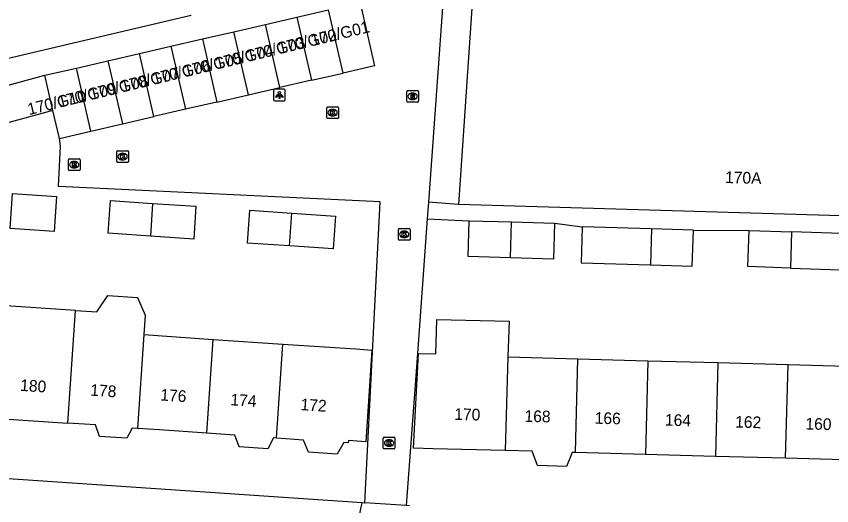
# Model space of a CAD drawing. Extents: x 159053 to 160041, y 380450 to 381422.
# Drawn here: x 159304.1 to 159374, y 381196.2 to 381238.1 of the extents above; entities that cross this region are included whole.
import ezdxf

# ---------------------------------------------------------------- set-up
doc = ezdxf.new("R2010")
doc.units = 0
for name, color, linetype in [('IMGEO_Kolk', 7, 'Continuous'), ('IMGEO_Lichtpunt', 7, 'Continuous'), ('IMGEO_Pand', 7, 'Continuous'), ('IMGEO_Pand_nummerreeks', 7, 'Continuous'), ('IMGEO_Rijbaan_lokaal_open', 7, 'Continuous'), ('IMGEO_Rioolput', 7, 'Continuous'), ('IMGEO_Voetpad_open', 7, 'Continuous')]:
    doc.layers.add(name, color=color, linetype=linetype)

msp = doc.modelspace()

# ---------------------------------------------------------------- linework, layer by layer
at = {"layer": 'IMGEO_Kolk'}
for p, q in [((159330.708, 381229.42), (159330.708, 381230.272)), ((159330.783, 381230.346), (159331.635, 381230.346)), ((159331.196, 381230.126), (159331.221, 381230.126)), ((159331.709, 381230.272), (159331.709, 381229.42)), ((159331.219, 381229.566), (159331.194, 381229.566)), ((159331.635, 381229.346), (159330.783, 381229.346)), ((159312.697, 381225.665), (159312.697, 381226.517)), ((159312.772, 381226.591), (159313.624, 381226.591)), ((159313.185, 381226.371), (159313.21, 381226.371)), ((159313.698, 381226.517), (159313.698, 381225.665)), ((159313.624, 381225.591), (159312.772, 381225.591)), ((159313.208, 381225.811), (159313.183, 381225.811)), ((159336.848, 381218.992), (159336.848, 381219.844)), ((159336.923, 381219.918), (159337.775, 381219.918)), ((159337.336, 381219.698), (159337.361, 381219.698)), ((159337.849, 381219.844), (159337.849, 381218.992)), ((159337.775, 381218.918), (159336.923, 381218.918)), ((159337.359, 381219.138), (159337.334, 381219.138)), ((159335.556, 381201.107), (159335.556, 381201.959)), ((159335.631, 381202.033), (159336.483, 381202.033)), ((159336.044, 381201.813), (159336.069, 381201.813)), ((159336.557, 381201.959), (159336.557, 381201.107)), ((159336.483, 381201.033), (159335.631, 381201.033)), ((159336.067, 381201.253), (159336.042, 381201.253))]:
    msp.add_line(p, q, dxfattribs=at)
for points in [[(159330.708, 381229.42), (159330.708, 381230.272)], [(159330.783, 381230.346), (159331.635, 381230.346)], [(159331.709, 381230.272), (159331.709, 381229.42)], [(159331.029, 381230.046), (159331.152, 381230.046), (159331.152, 381229.895), (159331.282, 381230.046), (159331.446, 381230.046), (159331.3, 381229.895), (159331.453, 381229.646), (159331.301, 381229.646), (159331.216, 381229.81), (159331.152, 381229.743), (159331.152, 381229.646), (159331.029, 381229.646), (159331.029, 381230.046)], [(159331.635, 381229.346), (159330.783, 381229.346)], [(159312.697, 381225.665), (159312.697, 381226.517)], [(159312.772, 381226.591), (159313.624, 381226.591)], [(159313.018, 381226.291), (159313.141, 381226.291), (159313.141, 381226.14), (159313.271, 381226.291), (159313.435, 381226.291), (159313.289, 381226.14), (159313.442, 381225.891), (159313.29, 381225.891), (159313.205, 381226.055), (159313.141, 381225.988), (159313.141, 381225.891), (159313.018, 381225.891), (159313.018, 381226.291)], [(159313.698, 381226.517), (159313.698, 381225.665)], [(159313.624, 381225.591), (159312.772, 381225.591)], [(159336.848, 381218.992), (159336.848, 381219.844)], [(159336.923, 381219.918), (159337.775, 381219.918)], [(159337.169, 381219.618), (159337.292, 381219.618), (159337.292, 381219.467), (159337.422, 381219.618), (159337.586, 381219.618), (159337.44, 381219.467), (159337.593, 381219.218), (159337.441, 381219.218), (159337.356, 381219.382), (159337.292, 381219.315), (159337.292, 381219.218), (159337.169, 381219.218), (159337.169, 381219.618)], [(159337.849, 381219.844), (159337.849, 381218.992)], [(159337.775, 381218.918), (159336.923, 381218.918)], [(159335.556, 381201.107), (159335.556, 381201.959)], [(159335.631, 381202.033), (159336.483, 381202.033)], [(159335.877, 381201.733), (159336, 381201.733), (159336, 381201.582), (159336.13, 381201.733), (159336.294, 381201.733), (159336.148, 381201.582), (159336.301, 381201.333), (159336.149, 381201.333), (159336.064, 381201.497), (159336, 381201.43), (159336, 381201.333), (159335.877, 381201.333), (159335.877, 381201.733)], [(159336.557, 381201.959), (159336.557, 381201.107)], [(159336.483, 381201.033), (159335.631, 381201.033)]]:
    msp.add_lwpolyline(points, dxfattribs=at)
for centre, start, end in [((159330.785, 381230.27), 91.55205, 178.44795), ((159330.785, 381230.27), 91.55205, 178.44795), ((159331.633, 381230.27), 1.55205, 88.44795), ((159331.633, 381230.27), 1.55205, 88.44795), ((159330.785, 381229.422), 181.55205, 268.44795), ((159330.785, 381229.422), 181.55205, 268.44795), ((159331.633, 381229.422), 271.55205, 358.44795), ((159331.633, 381229.422), 271.55205, 358.44795), ((159312.774, 381226.515), 91.55205, 178.44795), ((159312.774, 381226.515), 91.55205, 178.44795), ((159313.622, 381226.515), 1.55205, 88.44795), ((159313.622, 381226.515), 1.55205, 88.44795), ((159312.774, 381225.667), 181.55205, 268.44795), ((159312.774, 381225.667), 181.55205, 268.44795), ((159313.622, 381225.667), 271.55205, 358.44795), ((159313.622, 381225.667), 271.55205, 358.44795), ((159336.925, 381219.842), 91.55205, 178.44795), ((159336.925, 381219.842), 91.55205, 178.44795), ((159337.773, 381219.842), 1.55205, 88.44795), ((159337.773, 381219.842), 1.55205, 88.44795), ((159336.925, 381218.994), 181.55205, 268.44795), ((159336.925, 381218.994), 181.55205, 268.44795), ((159337.773, 381218.994), 271.55205, 358.44795), ((159337.773, 381218.994), 271.55205, 358.44795), ((159335.633, 381201.957), 91.55205, 178.44795), ((159335.633, 381201.957), 91.55205, 178.44795), ((159336.481, 381201.957), 1.55205, 88.44795), ((159336.481, 381201.957), 1.55205, 88.44795), ((159335.633, 381201.109), 181.55205, 268.44795), ((159335.633, 381201.109), 181.55205, 268.44795), ((159336.481, 381201.109), 271.55205, 358.44795), ((159336.481, 381201.109), 271.55205, 358.44795)]:
    msp.add_arc(centre, 0.0765, start, end, dxfattribs=at)
for centre, major_axis, ratio, start_param, end_param in [((159331.195, 381229.846), (-0.387, 0.002), 0.722429, 4.712389, 7.853982), ((159331.22, 381229.846), (-0.39, 0.002), 0.717154, 1.570796, 4.712389), ((159313.184, 381226.091), (-0.387, 0.002), 0.722429, 4.712389, 7.853982), ((159313.209, 381226.091), (-0.39, 0.002), 0.717154, 1.570796, 4.712389), ((159337.335, 381219.418), (-0.387, 0.002), 0.722429, 4.712389, 7.853982), ((159337.36, 381219.418), (-0.39, 0.002), 0.717154, 1.570796, 4.712389), ((159336.043, 381201.533), (-0.387, 0.002), 0.722429, 4.712389, 7.853982), ((159336.068, 381201.533), (-0.39, 0.002), 0.717154, 1.570796, 4.712389)]:
    msp.add_ellipse(centre, major_axis=major_axis, ratio=ratio, start_param=start_param, end_param=end_param, dxfattribs=at)
at = {"layer": 'IMGEO_Lichtpunt'}
for p, q in [((159326.15, 381231.764), (159326.15, 381230.957)), ((159326.15, 381231.764), (159326.15, 381230.957)), ((159327.052, 381231.859), (159326.244, 381231.859)), ((159327.052, 381231.859), (159326.244, 381231.859)), ((159327.146, 381230.957), (159327.146, 381231.764)), ((159327.146, 381230.957), (159327.146, 381231.764)), ((159326.244, 381230.863), (159327.052, 381230.863)), ((159326.244, 381230.863), (159327.052, 381230.863))]:
    msp.add_line(p, q, dxfattribs=at)
for points in [[(159326.524, 381231.428), (159326.563, 381231.4), (159326.375, 381231.138), (159326.337, 381231.165), (159326.524, 381231.428)], [(159326.626, 381231.38), (159326.673, 381231.38), (159326.673, 381231.058), (159326.626, 381231.058), (159326.626, 381231.38)], [(159326.736, 381231.4), (159326.774, 381231.427), (159326.961, 381231.165), (159326.922, 381231.137), (159326.736, 381231.4)]]:
    msp.add_lwpolyline(points, dxfattribs=at)
msp.add_circle((159326.649, 381231.562), 0.0994, dxfattribs=at)
for centre, start, end in [((159326.244, 381231.764), 90, 180), ((159326.244, 381231.764), 90, 180), ((159327.052, 381231.764), 0, 90), ((159327.052, 381231.764), 0, 90), ((159326.244, 381230.957), 180, 270), ((159326.244, 381230.957), 180, 270), ((159327.052, 381230.957), 270, 0), ((159327.052, 381230.957), 270, 360)]:
    msp.add_arc(centre, 0.0946, start, end, dxfattribs=at)
at = {"layer": 'IMGEO_Pand'}
for points in [[(159360.41, 381244.692), (159353.523, 381243.347), (159344.026, 381241.492), (159343.33, 381241.356), (159342.009, 381221.978)], [(159319.072, 381238.181), (159296.805, 381232.95), (159294.359, 381243.365)], [(159333.558, 381239.278), (159333.591, 381239.134), (159334.803, 381233.87), (159332.1, 381233.248)], [(159328.152, 381238.034), (159330.855, 381238.656)], [(159332.1, 381233.248), (159330.855, 381238.656)], [(159325.45, 381237.411), (159328.152, 381238.034)], [(159328.152, 381238.034), (159329.397, 381232.626)], [(159322.747, 381236.789), (159325.45, 381237.411)], [(159326.694, 381232.004), (159325.45, 381237.411)], [(159320.044, 381236.167), (159322.747, 381236.789)], [(159323.992, 381231.382), (159322.747, 381236.789)], [(159317.341, 381235.545), (159320.044, 381236.167)], [(159320.044, 381236.167), (159321.289, 381230.759)], [(159314.638, 381234.923), (159317.341, 381235.545)], [(159317.341, 381235.545), (159318.586, 381230.137)], [(159309.233, 381233.678), (159311.936, 381234.3)], [(159311.936, 381234.3), (159314.638, 381234.923)], [(159311.936, 381234.3), (159313.18, 381228.893)], [(159315.883, 381229.515), (159314.638, 381234.923)], [(159306.53, 381233.056), (159309.233, 381233.678)], [(159310.478, 381228.271), (159309.233, 381233.678)], [(159307.223, 381230.047), (159303.229, 381228.962), (159302.42, 381231.94), (159306.53, 381233.056)], [(159307.223, 381230.047), (159306.53, 381233.056)], [(159329.397, 381232.626), (159332.1, 381233.248)], [(159329.397, 381232.626), (159326.694, 381232.004)], [(159323.992, 381231.382), (159326.694, 381232.004)], [(159321.289, 381230.759), (159323.992, 381231.382)], [(159318.586, 381230.137), (159315.883, 381229.515)], [(159321.289, 381230.759), (159318.586, 381230.137)], [(159307.775, 381227.649), (159307.223, 381230.047)], [(159313.18, 381228.893), (159315.883, 381229.515)], [(159310.478, 381228.271), (159313.18, 381228.893)], [(159307.775, 381227.649), (159310.478, 381228.271)], [(159303.764, 381222.916), (159307.529, 381222.662), (159307.327, 381219.671), (159303.562, 381219.925), (159303.764, 381222.916)], [(159315.578, 381219.273), (159311.97, 381219.517), (159312.16, 381222.322), (159315.767, 381222.079)], [(159315.767, 381222.079), (159319.49, 381221.828), (159319.3, 381219.022), (159315.578, 381219.273)], [(159315.767, 381222.079), (159315.578, 381219.273)], [(159391.193, 381220.523), (159342.009, 381221.978)], [(159327.508, 381218.43), (159323.919, 381218.672), (159324.108, 381221.48), (159327.698, 381221.238)], [(159327.698, 381221.238), (159331.456, 381220.984), (159331.267, 381218.177), (159327.508, 381218.43)], [(159327.508, 381218.43), (159327.698, 381221.238)], [(159346.462, 381217.405), (159342.846, 381217.512), (159342.932, 381220.587)], [(159342.932, 381220.587), (159346.554, 381220.48)], [(159346.462, 381217.405), (159346.554, 381220.48)], [(159350.254, 381220.37), (159350.162, 381217.295), (159346.462, 381217.405)], [(159346.554, 381220.48), (159350.254, 381220.37)], [(159352.624, 381220.068), (159352.532, 381216.978), (159358.471, 381216.802)], [(159358.553, 381219.892), (159352.624, 381220.068)], [(159358.553, 381219.892), (159358.471, 381216.802)], [(159358.471, 381216.802), (159362.056, 381216.695), (159362.148, 381219.785)], [(159362.148, 381219.785), (159358.553, 381219.892)], [(159370.488, 381216.525), (159366.828, 381216.653), (159366.937, 381219.762)], [(159366.937, 381219.762), (159370.571, 381219.635)], [(159370.571, 381219.635), (159370.488, 381216.525)], [(159376.578, 381219.425), (159370.571, 381219.635)], [(159370.488, 381216.525), (159376.495, 381216.314), (159376.498, 381216.442)], [(159309.154, 381212.902), (159310.999, 381212.777), (159311.922, 381214.171), (159314.488, 381213.998), (159315.121, 381212.499), (159315.008, 381210.825)], [(159309.154, 381212.902), (159303.188, 381213.306)], [(159308.503, 381203.242), (159309.154, 381212.902)], [(159346.02, 381200.89), (159339.839, 381201.05), (159338.14, 381201.094), (159338.585, 381209.218), (159340.049, 381209.18), (159340.134, 381212.13), (159346.358, 381211.966), (159346.235, 381208.918)], [(159315.008, 381210.825), (159314.466, 381202.789)], [(159315.008, 381210.825), (159320.974, 381210.421)], [(159320.432, 381202.38), (159320.974, 381210.421)], [(159320.974, 381210.421), (159326.941, 381210.018)], [(159326.941, 381210.018), (159333.196, 381209.595), (159334.585, 381209.5), (159334.046, 381201.652), (159332.57, 381201.754), (159332.556, 381201.554), (159332.16, 381201.573), (159331.61, 381200.581), (159329.148, 381200.75), (159328.719, 381201.792), (159326.398, 381201.966)], [(159326.398, 381201.966), (159326.941, 381210.018)], [(159346.235, 381208.918), (159346.02, 381200.89)], [(159346.235, 381208.918), (159352.243, 381208.754)], [(159352.028, 381200.719), (159352.243, 381208.754)], [(159352.243, 381208.754), (159358.251, 381208.591)], [(159358.251, 381208.591), (159358.036, 381200.555)], [(159358.251, 381208.591), (159364.259, 381208.427)], [(159364.259, 381208.427), (159364.044, 381200.391)], [(159364.259, 381208.427), (159370.267, 381208.263)], [(159370.052, 381200.227), (159370.267, 381208.263)], [(159370.267, 381208.263), (159376.275, 381208.099)], [(159302.537, 381203.644), (159308.503, 381203.242)], [(159314.466, 381202.789), (159314.008, 381202.82), (159313.55, 381201.941), (159311.216, 381202.098), (159310.861, 381203.083), (159308.503, 381203.242)], [(159320.432, 381202.38), (159316.356, 381202.659), (159314.466, 381202.789)], [(159326.398, 381201.966), (159326.146, 381201.985), (159325.646, 381201.039), (159323.182, 381201.208), (159322.811, 381202.217), (159320.432, 381202.38)], [(159352.028, 381200.719), (159351.758, 381200.726), (159351.262, 381199.524), (159348.768, 381199.598), (159348.332, 381200.83), (159346.02, 381200.89)], [(159358.036, 381200.555), (159352.028, 381200.719)], [(159364.044, 381200.391), (159358.036, 381200.555)], [(159370.052, 381200.227), (159364.044, 381200.391)], [(159376.06, 381200.063), (159370.052, 381200.227)]]:
    msp.add_lwpolyline(points, dxfattribs=at)
at = {"layer": 'IMGEO_Rijbaan_lokaal_open'}
for points in [[(159335.696, 381239.745), (159340.789, 381240.858), (159339.422, 381222.167)], [(159333.982, 381196.416), (159335.297, 381222.211), (159307.687, 381223.515), (159307.881, 381226.982), (159307.775, 381227.649)], [(159339.422, 381222.167), (159339.319, 381220.746)], [(159339.319, 381220.746), (159338.476, 381209.221), (159337.521, 381196.176)], [(159337.521, 381196.176), (159333.982, 381196.416)]]:
    msp.add_lwpolyline(points, dxfattribs=at)
at = {"layer": 'IMGEO_Rioolput'}
for p, q in [((159337.569, 381230.825), (159337.569, 381231.677)), ((159337.644, 381231.751), (159338.496, 381231.751)), ((159338.057, 381231.531), (159338.082, 381231.531)), ((159338.57, 381231.677), (159338.57, 381230.825)), ((159338.08, 381230.971), (159338.055, 381230.971)), ((159338.496, 381230.751), (159337.644, 381230.751)), ((159308.545, 381224.964), (159308.545, 381225.816)), ((159308.62, 381225.89), (159309.472, 381225.89)), ((159309.033, 381225.67), (159309.058, 381225.67)), ((159309.546, 381225.816), (159309.546, 381224.964)), ((159309.472, 381224.89), (159308.62, 381224.89)), ((159309.056, 381225.11), (159309.031, 381225.11))]:
    msp.add_line(p, q, dxfattribs=at)
for points in [[(159337.569, 381230.825), (159337.569, 381231.677)], [(159337.644, 381231.751), (159338.496, 381231.751)], [(159338.57, 381231.677), (159338.57, 381230.825)], [(159338.158, 381231.449), (159337.906, 381231.451), (159337.906, 381231.051)], [(159337.906, 381231.051), (159338.03, 381231.051), (159338.03, 381231.213), (159338.041, 381231.213)], [(159338.084, 381231.37), (159338.03, 381231.37), (159338.03, 381231.289)], [(159338.03, 381231.289), (159338.082, 381231.289)], [(159338.088, 381231.184), (159338.159, 381231.051), (159338.299, 381231.051), (159338.234, 381231.177)], [(159338.496, 381230.751), (159337.644, 381230.751)], [(159308.545, 381224.964), (159308.545, 381225.816)], [(159308.62, 381225.89), (159309.472, 381225.89)], [(159309.134, 381225.588), (159308.882, 381225.59), (159308.882, 381225.19)], [(159308.882, 381225.19), (159309.006, 381225.19), (159309.006, 381225.352), (159309.017, 381225.352)], [(159309.06, 381225.509), (159309.006, 381225.509), (159309.006, 381225.428)], [(159309.006, 381225.428), (159309.058, 381225.428)], [(159309.064, 381225.323), (159309.135, 381225.19), (159309.275, 381225.19), (159309.21, 381225.316)], [(159309.546, 381225.816), (159309.546, 381224.964)], [(159309.472, 381224.89), (159308.62, 381224.89)]]:
    msp.add_lwpolyline(points, dxfattribs=at)
for centre, radius, start, end in [((159337.646, 381231.675), 0.0765, 91.55205, 178.44795), ((159337.646, 381231.675), 0.0765, 91.55205, 178.44795), ((159338.494, 381231.675), 0.0765, 1.55205, 88.44795), ((159338.494, 381231.675), 0.0765, 1.55205, 88.44795), ((159337.646, 381230.827), 0.0765, 181.55205, 268.44795), ((159337.646, 381230.827), 0.0765, 181.55205, 268.44795), ((159338.04, 381231.16), 0.0533, 26.02933, 88.69889), ((159338.066, 381231.478), 0.19, 274.7715, 282.96867), ((159338.09, 381231.274), 0.0964, 77.00612, 93.18647), ((159338.104, 381231.331), 0.0378, 276.66336, 79.67722), ((159338.157, 381231.339), 0.109, 350.36119, 89.41601), ((159338.155, 381231.339), 0.112, 277.58423, 350.98172), ((159338.139, 381231.124), 0.108, 29.51342, 73.79051), ((159338.494, 381230.827), 0.0765, 271.55205, 358.44795), ((159338.494, 381230.827), 0.0765, 271.55205, 358.44795), ((159308.622, 381225.814), 0.0765, 91.55205, 178.44795), ((159308.622, 381225.814), 0.0765, 91.55205, 178.44795), ((159309.016, 381225.299), 0.0533, 26.02933, 88.69889), ((159309.042, 381225.617), 0.19, 274.7715, 282.96867), ((159309.066, 381225.413), 0.0964, 77.00612, 93.18647), ((159309.08, 381225.47), 0.0378, 276.66336, 79.67722), ((159309.133, 381225.478), 0.109, 350.36119, 89.41601), ((159309.131, 381225.478), 0.112, 277.58423, 350.98172), ((159309.115, 381225.263), 0.108, 29.51342, 73.79051), ((159309.47, 381225.814), 0.0765, 1.55205, 88.44795), ((159309.47, 381225.814), 0.0765, 1.55205, 88.44795), ((159308.622, 381224.966), 0.0765, 181.55205, 268.44795), ((159308.622, 381224.966), 0.0765, 181.55205, 268.44795), ((159309.47, 381224.966), 0.0765, 271.55205, 358.44795), ((159309.47, 381224.966), 0.0765, 271.55205, 358.44795)]:
    msp.add_arc(centre, radius, start, end, dxfattribs=at)
for centre, major_axis, ratio, start_param, end_param in [((159338.056, 381231.251), (-0.387, 0.002), 0.722429, 4.712389, 7.853982), ((159338.081, 381231.251), (-0.39, 0.002), 0.717154, 1.570796, 4.712389), ((159309.032, 381225.39), (-0.387, 0.002), 0.722429, 4.712389, 7.853982), ((159309.057, 381225.39), (-0.39, 0.002), 0.717154, 1.570796, 4.712389)]:
    msp.add_ellipse(centre, major_axis=major_axis, ratio=ratio, start_param=start_param, end_param=end_param, dxfattribs=at)
at = {"layer": 'IMGEO_Voetpad_open'}
for points in [[(159342.009, 381221.978), (159339.422, 381222.167)], [(159339.319, 381220.746), (159342.932, 381220.587)], [(159350.254, 381220.37), (159352.624, 381220.068)], [(159362.148, 381219.785), (159366.937, 381219.762)], [(159278.092, 381200.211), (159333.735, 381196.433)], [(159333.024, 381193.003), (159333.735, 381196.433)], [(159333.735, 381196.433), (159333.982, 381196.416)], [(159337.817, 381196.156), (159337.521, 381196.176)]]:
    msp.add_lwpolyline(points, dxfattribs=at)

# ---------------------------------------------------------------- texts
at = {"layer": 'IMGEO_Pand_nummerreeks'}
for s, rotation, p in [('170/G01', 13.67131, (159329.473, 381235.549)), ('170/G02', 13.67131, (159326.662, 381234.865)), ('170/G04', 13.67131, (159321.272, 381233.554)), ('170/G03', 13.67131, (159323.97, 381234.21)), ('170/G05', 13.67131, (159318.575, 381232.898)), ('170/G06', 13.67131, (159315.877, 381232.241)), ('170/G07', 13.67131, (159313.179, 381231.585)), ('170/G08', 13.67131, (159310.484, 381230.93)), ('170/G09', 13.67131, (159307.78, 381230.272)), ('170/G10', 13.67077, (159305.176, 381229.638)), ('170A', 358.30404, (159364.86, 381223.823)), ('180', 356.07524, (159304.388, 381206.013)), ('178', 356.07524, (159310.402, 381205.6)), ('176', 356.07324, (159316.41, 381205.188)), ('174', 356.07324, (159322.423, 381204.775)), ('172', 356.07524, (159328.436, 381204.362)), ('170', 358.43583, (159341.637, 381203.523)), ('168', 358.43808, (159347.66, 381203.358)), ('166', 358.43808, (159353.679, 381203.193)), ('164', 358.43808, (159359.703, 381203.029)), ('162', 358.43808, (159365.725, 381202.865)), ('160', 358.43808, (159371.754, 381202.701))]:
    msp.add_text(s, height=1, rotation=rotation, dxfattribs=at).set_placement(p)

doc.saveas('drawing.dxf')
